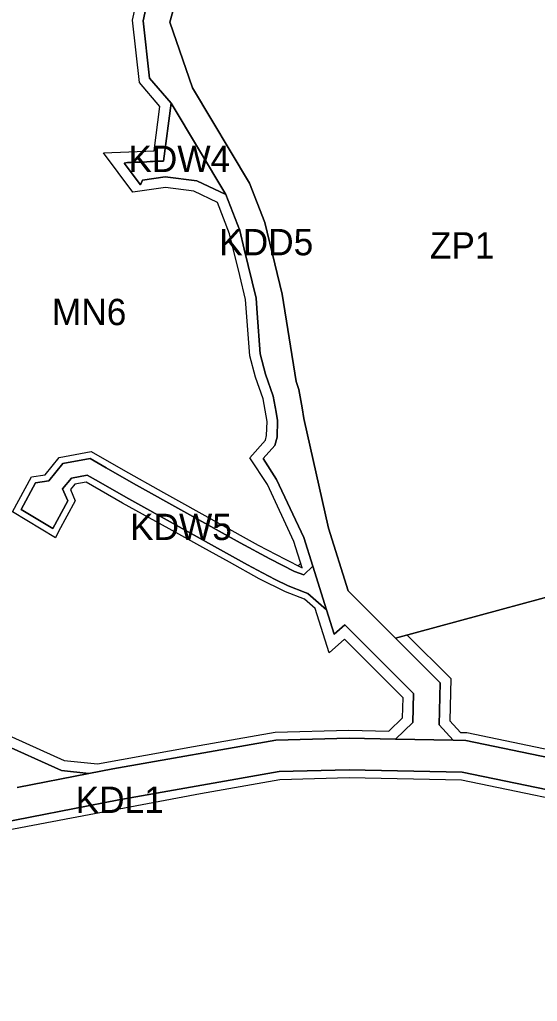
# Model space of a CAD drawing. Extents: x 7439486 to 7443435, y 5551288 to 5554556.
# Drawn here: x 7441655.2 to 7441851.7, y 5553243.9 to 5553616.6 of the extents above; entities that cross this region are included whole.
import ezdxf

# ---------------------------------------------------------------- set-up
doc = ezdxf.new("R2010")
doc.units = 0
for name, color, linetype in [('linie_rozgraniczajace', 7, 'Continuous'), ('linie_zabudowy_nieprzekraczalne', 7, 'Continuous'), ('oznaczenia_przeznaczen', 7, 'Continuous')]:
    doc.layers.add(name, color=color, linetype=linetype)

msp = doc.modelspace()

# ---------------------------------------------------------------- linework, layer by layer
at = {"layer": 'linie_rozgraniczajace'}
for points in [[(7441706.94, 5553638.55), (7441702.12, 5553616.12), (7441704.49, 5553594.39), (7441712.65, 5553584.8), (7441709.78, 5553562.85), (7441708.98, 5553562.82), (7441708.17, 5553562.79), (7441707.67, 5553562.77), (7441705.92, 5553562.7), (7441704.67, 5553562.65), (7441703.42, 5553562.6), (7441701.18, 5553562.5), (7441698.68, 5553562.4), (7441697.38, 5553562.35), (7441696.08, 5553562.3), (7441695.49, 5553562.22), (7441694.9, 5553562.13), (7441701.08, 5553553.85), (7441701.83, 5553555.6), (7441710.46, 5553556.85), (7441722.44, 5553555.33), (7441733.43, 5553550.11), (7441736.07, 5553543.3), (7441738.71, 5553536.5), (7441740.46, 5553529.47), (7441744.92, 5553510.85), (7441745.3, 5553505.14), (7441746.49, 5553489.63), (7441748.51, 5553481.95), (7441751.44, 5553473.65), (7441752.53, 5553467.49), (7441753.08, 5553464.36), (7441752.92, 5553458.05), (7441752.05, 5553454.95), (7441747.6, 5553449.9), (7441752.73, 5553442.03), (7441763.03, 5553419.93), (7441766.43, 5553409.14), (7441763.02, 5553405.76), (7441759.52, 5553407.12), (7441750.1, 5553411.81), (7441738.92, 5553418), (7441718.64, 5553429.24), (7441698.4, 5553440.46), (7441688.08, 5553446.39), (7441681.93, 5553449.93), (7441671.6, 5553448.03), (7441666.24, 5553441.48), (7441661.28, 5553440.71), (7441655.83, 5553430.65), (7441667.81, 5553423.37), (7441673.53, 5553433.94), (7441671.5, 5553438.43), (7441674.85, 5553442.53), (7441680.85, 5553443.63), (7441685.1, 5553441.19), (7441695.45, 5553435.24), (7441715.73, 5553424), (7441736.01, 5553412.76), (7441741.66, 5553409.63), (7441747.3, 5553406.5), (7441752.2, 5553404.06), (7441757.1, 5553401.62), (7441763.54, 5553399.12), (7441764.57, 5553398.72), (7441771.69, 5553392.45), (7441774.6, 5553383.24), (7441778.62, 5553386.82), (7441804.71, 5553360.74), (7441804.43, 5553349.72), (7441797.86, 5553343.44), (7441780.22, 5553343.8), (7441752.47, 5553343.09), (7441690.6, 5553332.2), (7441681.45, 5553330.41), (7441671.1, 5553331.46), (7441622.6, 5553353.22)], [(7441715.77, 5553628.35), (7441712.24, 5553615.6), (7441720.8, 5553590.65), (7441742.45, 5553554.52), (7441748.26, 5553539.53), (7441754.84, 5553512.36), (7441760.08, 5553479.21), (7441761.15, 5553476.2), (7441762.38, 5553469.23), (7441763.1, 5553465.1), (7441772.37, 5553423.56), (7441779.89, 5553399.7), (7441797.85, 5553381.74), (7441814.82, 5553364.77), (7441814.41, 5553348.91), (7441819.72, 5553342.99), (7441797.86, 5553343.44), (7441804.43, 5553349.72), (7441804.71, 5553360.74), (7441778.62, 5553386.82), (7441774.6, 5553383.24), (7441771.69, 5553392.45), (7441766.43, 5553409.14), (7441763.03, 5553419.93), (7441752.73, 5553442.03), (7441747.6, 5553449.9), (7441752.05, 5553454.95), (7441752.92, 5553458.05), (7441753.08, 5553464.36), (7441752.53, 5553467.49), (7441751.44, 5553473.65), (7441748.51, 5553481.95), (7441746.49, 5553489.63), (7441745.3, 5553505.14), (7441744.92, 5553510.85), (7441740.46, 5553529.47), (7441738.71, 5553536.5), (7441736.07, 5553543.3), (7441733.43, 5553550.11), (7441723.04, 5553567.46), (7441712.65, 5553584.8), (7441704.49, 5553594.39), (7441702.12, 5553616.12), (7441706.94, 5553638.55)], [(7441712.24, 5553615.6), (7441715.77, 5553628.35)], [(7441950.47, 5553333.43), (7441950.26, 5553333.23), (7441950.05, 5553333.04), (7441949.84, 5553332.85), (7441949.63, 5553332.67), (7441928.52, 5553324.38), (7441924.88, 5553324.65), (7441903.12, 5553365.93), (7441882.64, 5553404.78), (7441837.94, 5553392.64), (7441797.85, 5553381.74), (7441779.89, 5553399.7), (7441772.37, 5553423.56), (7441763.1, 5553465.1), (7441762.38, 5553469.23), (7441761.15, 5553476.2), (7441760.08, 5553479.21), (7441754.84, 5553512.36), (7441748.26, 5553539.53), (7441742.45, 5553554.52), (7441720.8, 5553590.65), (7441712.24, 5553615.6)], [(7441622.6, 5553353.22), (7441671.1, 5553331.46), (7441681.45, 5553330.41), (7441654.23, 5553325.09)], [(7441654.23, 5553325.09), (7441681.45, 5553330.41), (7441690.6, 5553332.2), (7441752.47, 5553343.09), (7441780.22, 5553343.8), (7441797.86, 5553343.44), (7441819.72, 5553342.99), (7441824.52, 5553342.9), (7441905.74, 5553326.1)], [(7441625.43, 5553307.24), (7441692.79, 5553320.41), (7441753.67, 5553331.12), (7441780.26, 5553331.8), (7441823.17, 5553330.92), (7441904.06, 5553314.19), (7441904.54, 5553314.16), (7441906.16, 5553308.16), (7441890.69, 5553304.55), (7441896.75, 5553295.85), (7441898.88, 5553292.27), (7441901.92, 5553286.67), (7441904.97, 5553281.08), (7441907.04, 5553272.17), (7441908.22, 5553267.37), (7441909.4, 5553262.57), (7441908.24, 5553255.09), (7441907.09, 5553247.61), (7441907.63, 5553244.24), (7441911.71, 5553246.12), (7441911.64, 5553245.76), (7441910.26, 5553240.49)], [(7441904.06, 5553314.19), (7441823.17, 5553330.92), (7441780.26, 5553331.8), (7441753.67, 5553331.12), (7441692.79, 5553320.41), (7441625.43, 5553307.24)]]:
    msp.add_lwpolyline(points, dxfattribs=at)
for points in [[(7441694.9, 5553562.13), (7441695.49, 5553562.22), (7441696.08, 5553562.3), (7441697.38, 5553562.35), (7441698.68, 5553562.4), (7441701.18, 5553562.5), (7441703.42, 5553562.6), (7441704.67, 5553562.65), (7441705.92, 5553562.7), (7441707.67, 5553562.77), (7441708.17, 5553562.79), (7441708.98, 5553562.82), (7441709.78, 5553562.85), (7441712.65, 5553584.8), (7441723.04, 5553567.46), (7441733.43, 5553550.11), (7441722.44, 5553555.33), (7441710.46, 5553556.85), (7441701.83, 5553555.6), (7441701.08, 5553553.85)], [(7441655.83, 5553430.65), (7441661.28, 5553440.71), (7441666.24, 5553441.48), (7441671.6, 5553448.03), (7441681.93, 5553449.93), (7441688.08, 5553446.39), (7441698.4, 5553440.46), (7441718.64, 5553429.24), (7441738.92, 5553418), (7441750.1, 5553411.81), (7441759.52, 5553407.12), (7441763.02, 5553405.76), (7441766.43, 5553409.14), (7441771.69, 5553392.45), (7441764.57, 5553398.72), (7441763.54, 5553399.12), (7441757.1, 5553401.62), (7441752.2, 5553404.06), (7441747.3, 5553406.5), (7441741.66, 5553409.63), (7441736.01, 5553412.76), (7441715.73, 5553424), (7441695.45, 5553435.24), (7441685.1, 5553441.19), (7441680.85, 5553443.63), (7441674.85, 5553442.53), (7441671.5, 5553438.43), (7441673.53, 5553433.94), (7441667.81, 5553423.37)], [(7441797.85, 5553381.74), (7441837.94, 5553392.64), (7441882.64, 5553404.78), (7441903.12, 5553365.93), (7441924.88, 5553324.65), (7441905.74, 5553326.1), (7441824.52, 5553342.9), (7441819.72, 5553342.99), (7441814.41, 5553348.91), (7441814.82, 5553364.77)]]:
    msp.add_lwpolyline(points, close=True, dxfattribs=at)
at = {"layer": 'linie_zabudowy_nieprzekraczalne'}
for points in [[(7441648.3, 5553346.08), (7441672.15, 5553335.37), (7441684.7, 5553334.1), (7441721.11, 5553340.62), (7441752.17, 5553346.09), (7441780.15, 5553346.8), (7441795.27, 5553346.5), (7441800.47, 5553351.47), (7441800.67, 5553359.12), (7441778.46, 5553381.33), (7441772.64, 5553376.14), (7441767.34, 5553392.95), (7441763.25, 5553396.55), (7441756.09, 5553399.33), (7441746.14, 5553404.29), (7441734.8, 5553410.57), (7441724.66, 5553416.19), (7441714.52, 5553421.81), (7441694.22, 5553433.06), (7441680.4, 5553441), (7441676.2, 5553440.23), (7441674.51, 5553438.17), (7441676.32, 5553433.84), (7441670, 5553422.18), (7441668.75, 5553419.87), (7441652.5, 5553429.75), (7441659.7, 5553442.99), (7441664.91, 5553443.8), (7441670.24, 5553450.32), (7441682.38, 5553452.55), (7441694.48, 5553445.6), (7441709.74, 5553437.04), (7441729.99, 5553425.81), (7441745.7, 5553417.11), (7441755.9, 5553411.71), (7441762.45, 5553408.45), (7441759.29, 5553418.47), (7441749.22, 5553440.09), (7441742.59, 5553450.27), (7441748.44, 5553456.9), (7441748.93, 5553458.65), (7441749.07, 5553464.06), (7441747.56, 5553472.63), (7441744.69, 5553480.78), (7441742.53, 5553488.96), (7441740.95, 5553510.25), (7441738.76, 5553519.38), (7441734.89, 5553535.28), (7441730.28, 5553547.18), (7441721.3, 5553551.45), (7441710.5, 5553552.81), (7441698.19, 5553551.04), (7441687.07, 5553565.94), (7441706.25, 5553566.71), (7441708.45, 5553583.56), (7441700.65, 5553592.74), (7441698.07, 5553616.33), (7441703.17, 5553640.07)], [(7441760.88, 5553409.27), (7441761.88, 5553410.26)], [(7441802.29, 5553382.95), (7441818.86, 5553366.39), (7441818.45, 5553350.4), (7441822.45, 5553345.94), (7441824.86, 5553345.89), (7441865.51, 5553337.48), (7441906.16, 5553329.08), (7441923.14, 5553327.79)], [(7441626.02, 5553304.3), (7441674.9, 5553313.55), (7441723.77, 5553322.81), (7441753.97, 5553328.13), (7441780.26, 5553328.8), (7441822.83, 5553327.93), (7441881.43, 5553315.81), (7441889.04, 5553314.24), (7441882.48, 5553298.83), (7441888.34, 5553290.43), (7441895.54, 5553277.49), (7441899.21, 5553262.12), (7441897.21, 5553249.13), (7441906.07, 5553234.99)]]:
    msp.add_lwpolyline(points, dxfattribs=at)

# ---------------------------------------------------------------- texts
at = {"layer": 'oznaczenia_przeznaczen'}
for s, p in [('KDW4', (7441696.46, 5553558.68)), ('KDD5', (7441730.94, 5553527.09)), ('ZP1', (7441810.84, 5553525.85)), ('MN6', (7441667.45, 5553500.57)), ('KDW5', (7441697.11, 5553419)), ('KDL1', (7441676.45, 5553315.41))]:
    msp.add_text(s, height=10, dxfattribs=at).set_placement(p)

doc.saveas('drawing.dxf')
